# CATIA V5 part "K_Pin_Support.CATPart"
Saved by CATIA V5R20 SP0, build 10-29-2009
Part number: Pin_Support
Bounding box of the stored display mesh (mm): x -39.5 to 39.5, y 55.976 to 58.976, z 3.5 to 6.5
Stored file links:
  G:\Khaled_CFAO_2011\SIL\SIL_GR2\ctanaphiko\Khaled\CAD_ThinkMOTION\K_Pin_Support.CATPart
  G:\Khaled_CFAO_2011\SIL\SIL_GR2\ctanaphiko\CATIA\ctanaphiko.CATProduct
  G:\Khaled_CFAO_2011\SIL\SIL_GR2\ctanaphiko\Khaled\CAD_ThinkMOTION\K_Support_camera.CATPart
  G:\Khaled_CFAO_2011\SIL\SIL_GR2\ctanaphiko\CATIA\Squelette.CATPart
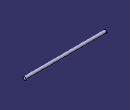
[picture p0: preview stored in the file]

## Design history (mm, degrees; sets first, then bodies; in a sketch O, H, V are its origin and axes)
External parameters (linked from other documents)
  External.Width_Leg_Support = 75 mm
AxisSystem1: origin (0, 0, 0), X (1, 0, 0), Y (0, 1, 0), Z (0, 0, 1)
Set1
  DatumCurve1: linked copy from another document
Body1 (main body)
  Sketch1 on YZ plane of AxisSystem1, origin (0, 0, 0), H (0, 1, 0), V (0, 0, 1)
    circle A1 centre (57.476, 5) radius 1.5
    reference projected circle E1 centre (57.476, 5) radius 1.5 from edge of DatumCurve1
    radius A1 = 1.5
    concentricity: A1 E1
  Pad1: profile Sketch1, direction (1, 0, 0), length 39.5 {= External.Width_Leg_Support /2+2mm}, mirrored extent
